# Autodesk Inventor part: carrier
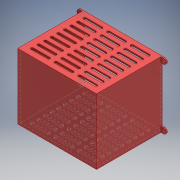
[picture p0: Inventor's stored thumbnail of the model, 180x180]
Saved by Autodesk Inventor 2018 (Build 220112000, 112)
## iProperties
Created: 2023-12
Part Number: carrier
Material: Generic
Document SubType Name: Modeling
Designer: DDUGKY
Density: 1 g/cm^3
Appearance: Smooth - Red
Author: DDUGKY
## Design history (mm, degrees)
sketch "Sketch1"
  geometry: L1 (150, 125)-(-150, 125); L2 (-150, 125)-(-150, -125); L3 (-150, -125)-(150, -125); L4 (150, -125)-(150, 125); L5 (150, 125)-(-150, -125); L6 (-150, 125)-(150, -125); 1 further point
  constraints: 12 end point, 2 midpoint, 2 parallel, 1 horizontal, 1 perpendicular
  dimensions: "d0" = 300 distance of L3.end L2.end; "d1" = 250 distance of L2.end L1.end
extrude "Extrusion1" new body sketch "Sketch1" distance "d2" = 250; taper "d3" = 0 deg
shell "Shell1" dims "d4" = 5
sketch "Sketch2"
  geometry: L1 (-150, 125)-(-160, 125); L2 (-160, 105)-(-150, 105); L3 (-150, 105)-(-150, 125); L4 (0, 0)-(0, -27.751); L5 (0, 0)-(22.341, 0); L6 (150, 125)-(160, 125); L7 (160, 105)-(150, 105); L8 (150, 105)-(150, 125); L9 (-150, -125)-(-160, -125); L10 (-160, -105)-(-150, -105); L11 (-150, -105)-(-150, -125); L12 (150, -125)-(160, -125); L13 (160, -105)-(150, -105); L14 (150, -105)-(150, -125); C1 r 3.75 at (-160, 115); C2 r 3.75 at (160, 115); C3 r 3.75 at (-160, -115); C4 r 3.75 at (160, -115); A1 r 10 centre (-160, 115) between (-160, 125) and (-160, 105); A2 r 10 centre (160, 115) between (160, 105) and (160, 125); A3 r 10 centre (-160, -115) between (-160, -105) and (-160, -125); A4 r 10 centre (160, -115) between (160, -125) and (160, -105)
  constraints: 28 end point, 18 symmetric about line, 8 centre point, 8 point on circle, 4 coincident, 1 horizontal, 1 vertical, 6 other
  dimensions: "d5" = 10 distance of L2.end L2.start; "d6" = 20 distance of L2.start L1.end; "d7" = 7.5 diameter of C1
extrude "Extrusion2" join sketch "Sketch2" distance "d8" = 5; taper "d9" = 0 deg
sketch "Sketch3"
  geometry: L1 (31.322, -23.601)-(-31.93, -23.601); L2 (31.322, -18.827)-(-31.93, -18.827); L3 (-31.93, -28.375)-(31.322, -28.375); L4 (-58.678, -23.601)-(-121.93, -23.601); L5 (-58.678, -18.827)-(-121.93, -18.827); L6 (-121.93, -28.375)-(-58.678, -28.375); L7 (121.322, -23.601)-(58.07, -23.601); L8 (121.322, -18.827)-(58.07, -18.827); L9 (58.07, -28.375)-(121.322, -28.375); L10 (31.322, -23.601)-(-31.93, -23.601); L11 (31.322, -18.827)-(-31.93, -18.827); L12 (-31.93, -28.375)-(31.322, -28.375); A1 r 4.774 centre (31.322, -23.601) between (31.322, -28.375) and (31.322, -18.827); A2 r 4.774 centre (-31.93, -23.601) between (-31.93, -18.827) and (-31.93, -28.375); A3 r 4.774 centre (-58.678, -23.601) between (-58.678, -28.375) and (-58.678, -18.827); A4 r 4.774 centre (-121.93, -23.601) between (-121.93, -18.827) and (-121.93, -28.375); A5 r 4.774 centre (121.322, -23.601) between (121.322, -28.375) and (121.322, -18.827); A6 r 4.774 centre (58.07, -23.601) between (58.07, -18.827) and (58.07, -28.375); A7 r 4.774 centre (31.322, -23.601) between (31.322, -28.375) and (31.322, -18.827); A8 r 4.774 centre (-31.93, -23.601) between (-31.93, -18.827) and (-31.93, -28.375); 4 further points
  constraints: 32 end point, 16 point on circle, 8 centre point, 4 tangent, 3 horizontal, 2 collinear, 1 midpoint, 1 parallel, 34 other
  dimensions: "d12" = 90 distance of L2.start L5.start; "d15" = 90 distance of L2.start L8.start
extrude "Extrusion3" cut sketch "Sketch3" stored distance "d18" = 280.75; taper "d19" = 0 deg
pattern_linear "Rectangular Pattern1" dims "d22" = 25
body "Solid1"
